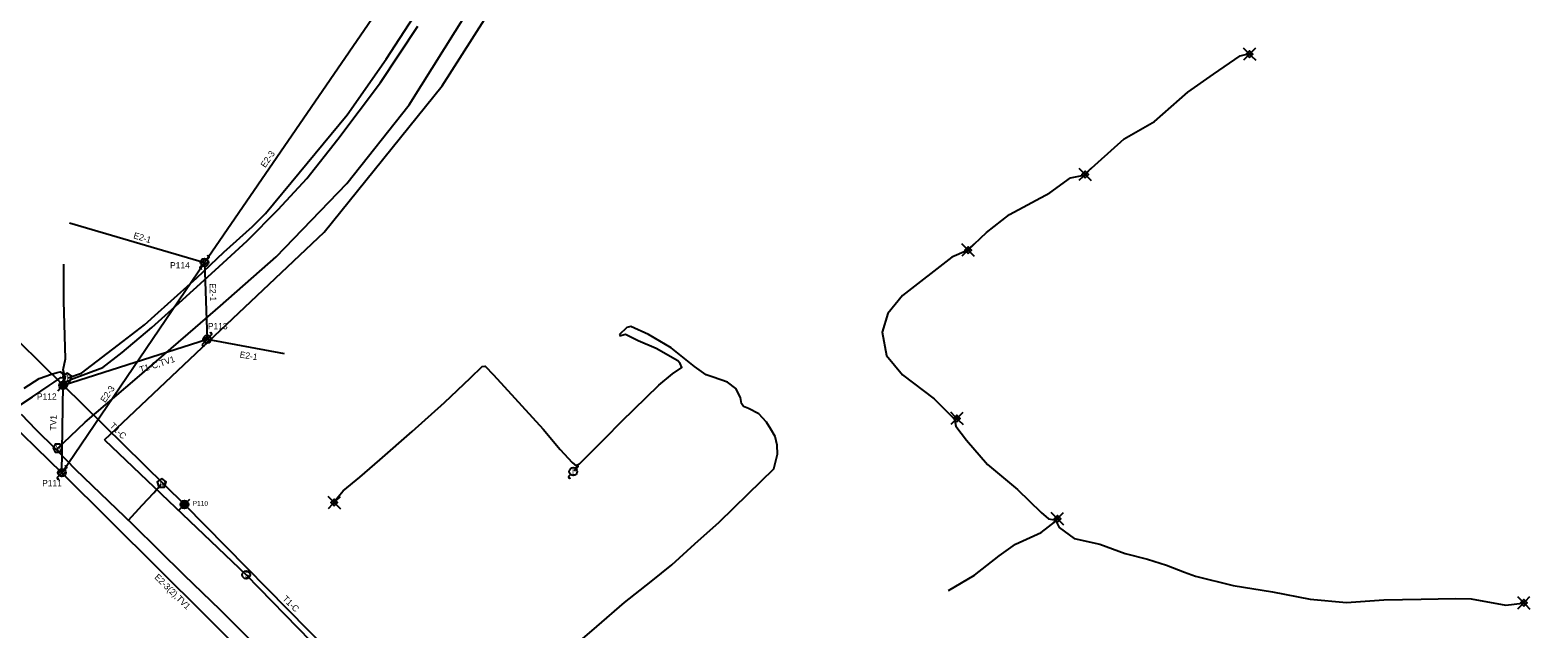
# Model space of a CAD drawing. Extents: x 1741604 to 1825760, y 1164229 to 1194908.
# Drawn here: x 1755425 to 1756379, y 1170189 to 1170568 of the extents above; entities that cross this region are included whole.
import ezdxf

# ---------------------------------------------------------------- set-up
doc = ezdxf.new("R2010")
doc.units = 0
for name, color, linetype in [('RD_EX_SU_Elec', 7, 'Continuous'), ('RD_EX_SU_H2O', 7, 'Continuous'), ('RD_EX_SU_Ovhd', 7, 'Continuous'), ('RD_EX_SU_Pole', 7, 'Continuous'), ('RD_EX_SU_Sewer', 7, 'Continuous'), ('RD_EX_SU_Telecom', 7, 'Continuous'), ('RD_EX_SU_TX_Pole', 7, 'Continuous')]:
    doc.layers.add(name, color=color, linetype=linetype)

# ---------------------------------------------------------------- blocks, each defined once
blk = doc.blocks.new('SUE_SMH')
at = {"layer": 'RD_EX_SU_Sewer'}
blk.add_circle((0, 0), 2.5, dxfattribs=at)
blk.add_text('S', height=3.57, dxfattribs=at).set_placement((-1.1, -1.79))

msp = doc.modelspace()

# ---------------------------------------------------------------- linework, layer by layer
at = {"layer": 'RD_EX_SU_Elec'}
msp.add_line((1755769.73, 1170288.79), (1755771.94, 1170292.51), dxfattribs=at)
for points in [[(1756092.94, 1170476.8), (1756117.55, 1170499.13), (1756136.8, 1170510.03), (1756157.82, 1170528.54), (1756174.09, 1170540.03), (1756190.91, 1170551.7), (1756196.05, 1170552.79)], [(1756018.81, 1170428.87), (1756030.47, 1170439.75), (1756045.03, 1170451.25), (1756070.52, 1170464.95), (1756083.65, 1170474.3), (1756092.12, 1170476.14)], [(1756017.8, 1170428.16), (1756008.58, 1170424.13), (1755977.33, 1170399.9), (1755968.08, 1170388.43), (1755964.43, 1170376.64), (1755967.1, 1170361.97), (1755977.19, 1170349.66), (1755997.36, 1170334.46), (1756009.95, 1170321.75)], [(1755764.15, 1170173.48), (1755783.87, 1170190.32), (1755801.35, 1170205.51), (1755818.14, 1170218.73), (1755831.29, 1170229.36), (1755845.85, 1170242.71), (1755861.2, 1170256.39), (1755879.67, 1170274.4), (1755895.87, 1170290.03), (1755898.13, 1170299.43), (1755898.05, 1170305.12), (1755896.64, 1170310.54), (1755894.02, 1170315.33), (1755891.25, 1170319.72), (1755886.27, 1170324.96), (1755879.88, 1170328.25), (1755876.6, 1170329.65), (1755875.38, 1170331.44), (1755874.71, 1170335.3), (1755871.77, 1170340.94), (1755866.63, 1170344.91), (1755857.41, 1170348.16), (1755853.09, 1170349.71), (1755845.62, 1170355.02), (1755830.83, 1170366.84), (1755816.52, 1170375.19), (1755805.26, 1170380.24), (1755802.74, 1170379.53), (1755797.92, 1170375.06)], [(1755618.1, 1170269.96), (1755623.39, 1170276.22), (1755633.75, 1170284.81), (1755646.57, 1170295.84), (1755666.96, 1170313.82), (1755687.48, 1170332.23), (1755703.98, 1170347.72), (1755711.25, 1170354.85), (1755713.07, 1170355.19), (1755718.51, 1170349.68), (1755749.77, 1170315.15), (1755760.69, 1170302.36), (1755768.14, 1170294.21), (1755770.98, 1170291.84), (1755772.95, 1170293.2), (1755780.25, 1170300.69), (1755789.11, 1170309.46), (1755799.38, 1170320.09), (1755823.12, 1170343.14), (1755831.66, 1170350.19), (1755837.58, 1170354.28), (1755836.65, 1170356.73), (1755835.13, 1170358.52), (1755821.44, 1170366.22), (1755809.99, 1170371.15), (1755802.05, 1170375.1), (1755798.27, 1170374.17)], [(1756010.36, 1170320.8), (1756011.01, 1170317.24), (1756017.76, 1170308.34), (1756030.98, 1170292.91), (1756050.1, 1170277.01), (1756065.02, 1170262.49), (1756069.77, 1170258.45), (1756073.45, 1170257.78)], [(1756006.39, 1170213.05), (1756022.78, 1170222.76), (1756038.42, 1170235.07), (1756048.77, 1170242.48), (1756065.02, 1170249.8), (1756074.27, 1170257.02)], [(1756074.51, 1170256.77), (1756076.39, 1170252.9), (1756085.89, 1170246.13), (1756102.17, 1170242.39), (1756118.29, 1170236.61), (1756132.4, 1170232.92), (1756144.33, 1170229.04), (1756155.71, 1170224.63), (1756162.64, 1170222.23), (1756186.51, 1170216.21), (1756211.5, 1170212.34), (1756235.26, 1170207.54), (1756258.17, 1170205.47), (1756281.96, 1170207.21), (1756305.43, 1170207.68), (1756327.12, 1170208.01), (1756337.21, 1170207.77), (1756359.06, 1170203.86), (1756369.7, 1170205.08)]]:
    msp.add_lwpolyline(points, dxfattribs=at)
at = {"layer": 'RD_EX_SU_H2O'}
for points in [[(1755441.66, 1170302.24), (1755460.1, 1170319.63), (1755492.98, 1170347.81), (1755529.94, 1170379.56), (1755545.71, 1170393.41), (1755580.96, 1170424.36), (1755625.65, 1170470.71), (1755664.97, 1170520.56), (1755702.01, 1170579.47)], [(1755419.51, 1170324.82), (1755428.9, 1170315.01), (1755440.94, 1170302.99), (1755442.22, 1170301.65), (1755453.83, 1170289.61), (1755469.55, 1170274.72), (1755490.11, 1170254.98), (1755522.61, 1170222.9), (1755545.21, 1170201.07), (1755581.64, 1170164.83), (1755584.47, 1170162.08), (1755603.36, 1170143.23), (1755654.48, 1170091.61), (1755673.95, 1170071.98), (1755722.41, 1170022.15)], [(1755487.36, 1170257.63), (1755496.08, 1170267.09), (1755503.52, 1170274.97), (1755508.06, 1170280.36)]]:
    msp.add_lwpolyline(points, dxfattribs=at)
for points in [[(1755445.45, 1170303.25), (1755444.01, 1170305.75), (1755441.12, 1170305.75), (1755439.68, 1170303.25), (1755441.12, 1170300.75), (1755444.01, 1170300.75)], [(1755508.49, 1170284.08), (1755505.59, 1170281.98), (1755506.7, 1170278.57), (1755510.29, 1170278.57), (1755511.39, 1170281.98)]]:
    msp.add_lwpolyline(points, close=True, dxfattribs=at)
at = {"layer": 'RD_EX_SU_Ovhd'}
for p, q in [((1755450.2, 1170445.81), (1755535.55, 1170420.8)), ((1755346.94, 1170440.97), (1755446.08, 1170343.01)), ((1755445.31, 1170287.7), (1755535.55, 1170420.8)), ((1755535.55, 1170420.8), (1755537.22, 1170372.19)), ((1755341.33, 1170388.64), (1755445.31, 1170287.7)), ((1755446.08, 1170343.01), (1755537.22, 1170372.19)), ((1755537.22, 1170372.19), (1755585.97, 1170363.18)), ((1755445.31, 1170287.7), (1755446.08, 1170343.01)), ((1755446.08, 1170343.01), (1755522.86, 1170267.55)), ((1755445.31, 1170287.7), (1755579.05, 1170154.72)), ((1755522.86, 1170267.55), (1755614.2, 1170174.75))]:
    msp.add_line(p, q, dxfattribs=at)
msp.add_lwpolyline([(1755535.55, 1170420.8), (1755660.75, 1170603.52)], dxfattribs=at)
at = {"layer": 'RD_EX_SU_Pole'}
for p, q in [((1756195.84, 1170551.64), (1756193.01, 1170548.81)), ((1756195.89, 1170553.74), (1756193.07, 1170556.57)), ((1756197.98, 1170553.8), (1756200.82, 1170556.64)), ((1756198.01, 1170551.62), (1756200.84, 1170548.79)), ((1756091.76, 1170475.43), (1756088.93, 1170472.61)), ((1756091.81, 1170477.54), (1756088.98, 1170480.37)), ((1756093.89, 1170477.6), (1756096.73, 1170480.44)), ((1756093.93, 1170475.42), (1756096.76, 1170472.59)), ((1756017.64, 1170427.59), (1756014.81, 1170424.77)), ((1756017.69, 1170429.7), (1756014.86, 1170432.53)), ((1756019.77, 1170429.75), (1756022.61, 1170432.59)), ((1756019.81, 1170427.58), (1756022.64, 1170424.75)), ((1755532.72, 1170417.97), (1755533.78, 1170419.03)), ((1755533.13, 1170420.15), (1755536.19, 1170423.21)), ((1755533.78, 1170419.03), (1755537.31, 1170422.57)), ((1755534.9, 1170418.38), (1755537.96, 1170421.45)), ((1755537.31, 1170422.57), (1755538.37, 1170423.63)), ((1755534.39, 1170369.36), (1755535.45, 1170370.42)), ((1755534.81, 1170371.54), (1755537.87, 1170374.6)), ((1755535.45, 1170370.42), (1755538.99, 1170373.95)), ((1755536.57, 1170369.77), (1755539.64, 1170372.83)), ((1755538.99, 1170373.95), (1755540.05, 1170375.01)), ((1756010.61, 1170321), (1756007.78, 1170318.17)), ((1756010.66, 1170323.11), (1756007.83, 1170325.93)), ((1756012.75, 1170323.16), (1756015.59, 1170326)), ((1756012.78, 1170320.98), (1756015.61, 1170318.16)), ((1755442.48, 1170284.87), (1755443.54, 1170285.93)), ((1755442.89, 1170287.05), (1755445.96, 1170290.12)), ((1755443.54, 1170285.93), (1755447.08, 1170289.47)), ((1755444.66, 1170285.29), (1755447.72, 1170288.35)), ((1755447.08, 1170289.47), (1755448.14, 1170290.53)), ((1755766.08, 1170285.56), (1755767.14, 1170286.62)), ((1755770.68, 1170290.16), (1755771.74, 1170291.22)), ((1755616.64, 1170269.8), (1755613.81, 1170272.63)), ((1755618.72, 1170269.86), (1755621.56, 1170272.7)), ((1755519.44, 1170264.12), (1755521.1, 1170265.78)), ((1755520.38, 1170267.22), (1755523.2, 1170270.03)), ((1755520.77, 1170266.18), (1755524.23, 1170269.64)), ((1755521.47, 1170265.47), (1755524.94, 1170268.94)), ((1755522.49, 1170265.07), (1755525.34, 1170267.93)), ((1755524.39, 1170265.56), (1755524.85, 1170266.02)), ((1755524.63, 1170269.32), (1755526.29, 1170270.97)), ((1755616.59, 1170267.69), (1755613.76, 1170264.87)), ((1755618.76, 1170267.68), (1755621.59, 1170264.85)), ((1756074.19, 1170257.51), (1756071.37, 1170254.68)), ((1756074.24, 1170259.61), (1756071.42, 1170262.44)), ((1756076.33, 1170259.67), (1756079.17, 1170262.51)), ((1756076.37, 1170257.49), (1756079.19, 1170254.66)), ((1756369.43, 1170206.3), (1756366.6, 1170209.13)), ((1756371.51, 1170206.36), (1756374.35, 1170209.2)), ((1756369.37, 1170204.19), (1756366.55, 1170201.37)), ((1756371.55, 1170204.18), (1756374.37, 1170201.35))]:
    msp.add_line(p, q, dxfattribs=at)
for points in [[(1756196.95, 1170550.56), (1756199.08, 1170552.68), (1756196.95, 1170554.8), (1756194.83, 1170552.68)], [(1756196.95, 1170551.98), (1756197.66, 1170552.68), (1756196.95, 1170553.39), (1756196.25, 1170552.68)], [(1756092.87, 1170474.36), (1756094.99, 1170476.48), (1756092.87, 1170478.6), (1756090.75, 1170476.48)], [(1756092.87, 1170475.77), (1756093.58, 1170476.48), (1756092.87, 1170477.19), (1756092.16, 1170476.48)], [(1756018.75, 1170426.52), (1756020.87, 1170428.64), (1756018.75, 1170430.76), (1756016.63, 1170428.64)], [(1756018.75, 1170427.93), (1756019.45, 1170428.64), (1756018.75, 1170429.35), (1756018.04, 1170428.64)], [(1756011.72, 1170319.92), (1756013.84, 1170322.04), (1756011.72, 1170324.17), (1756009.6, 1170322.04)], [(1756011.72, 1170321.34), (1756012.43, 1170322.04), (1756011.72, 1170322.75), (1756011.02, 1170322.04)], [(1755617.7, 1170266.62), (1755619.82, 1170268.74), (1755617.7, 1170270.86), (1755615.58, 1170268.74)], [(1755617.7, 1170268.03), (1755618.41, 1170268.74), (1755617.7, 1170269.45), (1755616.99, 1170268.74)], [(1756075.31, 1170256.43), (1756077.43, 1170258.55), (1756075.31, 1170260.67), (1756073.18, 1170258.55)], [(1756075.31, 1170257.85), (1756076.01, 1170258.55), (1756075.31, 1170259.26), (1756074.6, 1170258.55)], [(1756370.49, 1170203.12), (1756372.61, 1170205.24), (1756370.49, 1170207.36), (1756368.36, 1170205.24)], [(1756370.49, 1170204.53), (1756371.19, 1170205.24), (1756370.49, 1170205.95), (1756369.78, 1170205.24)]]:
    msp.add_lwpolyline(points, close=True, dxfattribs=at)
for centre in [(1755535.55, 1170420.8), (1755537.22, 1170372.19), (1755445.31, 1170287.7), (1755768.91, 1170288.39), (1755522.86, 1170267.55)]:
    msp.add_circle(centre, 2.5, dxfattribs=at)
for centre, start, end in [((1755533.25, 1170417.44), 135, 315), ((1755537.84, 1170424.16), 315, 135), ((1755534.92, 1170368.83), 135, 315), ((1755539.52, 1170375.54), 315, 135), ((1755447.61, 1170291.06), 315, 135), ((1755771.21, 1170291.75), 315, 135), ((1755443.01, 1170284.34), 135, 315), ((1755766.61, 1170285.03), 135, 315)]:
    msp.add_arc(centre, 0.75, start, end, dxfattribs=at)
at = {"layer": 'RD_EX_SU_Sewer'}
for points in [[(1755472.28, 1170308.43), (1755611.28, 1170440.07), (1755685.92, 1170532.6), (1755771.11, 1170666.36), (1755900.75, 1170895.13), (1755970.93, 1170995.72), (1756034.36, 1171088.88), (1756090.2, 1171167.02), (1756147.55, 1171225.76), (1756231.9, 1171306.77), (1756311.52, 1171366.34), (1756443.61, 1171443.81), (1756596.95, 1171527.35), (1756716.89, 1171571.4), (1756861.63, 1171600.26), (1756930.46, 1171628.36), (1757060.01, 1171710.39), (1757108.59, 1171767.1), (1757159.2, 1171859.25), (1757206.77, 1171953.42), (1757250.3, 1172017.89), (1757282.69, 1172067.18)], [(1755472.28, 1170308.43), (1755562.01, 1170223), (1755684.15, 1170097.75), (1755848.2, 1169927.49), (1755891.42, 1169870.58), (1755920.4, 1169827.47), (1756045.49, 1169608.65)]]:
    msp.add_lwpolyline(points, dxfattribs=at)
at = {"layer": 'RD_EX_SU_Telecom'}
for p, q in [((1755442.66, 1170339.59), (1755444.31, 1170341.24)), ((1755443.6, 1170342.68), (1755446.41, 1170345.49)), ((1755443.99, 1170341.65), (1755447.45, 1170345.11)), ((1755444.69, 1170340.93), (1755448.16, 1170344.41)), ((1755445.7, 1170340.54), (1755448.56, 1170343.39)), ((1755447.61, 1170341.02), (1755448.07, 1170341.49)), ((1755447.85, 1170344.78), (1755449.51, 1170346.43))]:
    msp.add_line(p, q, dxfattribs=at)
for points in [[(1755449.11, 1170347.65), (1755457.73, 1170350.8), (1755483.9, 1170370.75), (1755497.68, 1170381.21), (1755506.16, 1170389.1), (1755530.61, 1170411.02), (1755547.76, 1170427.26), (1755566.03, 1170443.65), (1755574.14, 1170451.88), (1755595.4, 1170477.57), (1755625.82, 1170514.33), (1755650.49, 1170549.56), (1755673.65, 1170585.08)], [(1755446.79, 1170344.44), (1755451.4, 1170346.81), (1755460.49, 1170350.22), (1755471.27, 1170354.25), (1755483.52, 1170363.87), (1755502.25, 1170379.57), (1755514.96, 1170391), (1755542.24, 1170415.97), (1755562.47, 1170434.47), (1755582.15, 1170454.24), (1755600.22, 1170474.01), (1755619.93, 1170498.75), (1755647, 1170534.73), (1755670.61, 1170570.42)], [(1755445.25, 1170344.06), (1755446.67, 1170346.87), (1755446.7, 1170350.47), (1755446.14, 1170352.74), (1755447.49, 1170359.74), (1755446.59, 1170396.26), (1755446.48, 1170419.76)], [(1755421.33, 1170341.29), (1755431, 1170347.4), (1755438.64, 1170350.17), (1755442.41, 1170351.15), (1755444.23, 1170351.54), (1755445.28, 1170351), (1755446.51, 1170349.43), (1755447.78, 1170348.08)], [(1755416.15, 1170328.72), (1755426.62, 1170335.77), (1755437.27, 1170342.91), (1755440.35, 1170345.05), (1755442.42, 1170346.51), (1755444.68, 1170348.06), (1755447.73, 1170347.81)], [(1755447.47, 1170347.06), (1755446.12, 1170345.44), (1755445.81, 1170344.48)]]:
    msp.add_lwpolyline(points, dxfattribs=at)
msp.add_lwpolyline([(1755448.64, 1170350.83), (1755445.79, 1170348.76), (1755446.88, 1170345.41), (1755450.41, 1170345.41), (1755451.49, 1170348.76)], close=True, dxfattribs=at)
msp.add_circle((1755446.08, 1170343.01), 2.5, dxfattribs=at)

# ---------------------------------------------------------------- block references
at = {"layer": 'RD_EX_SU_Sewer'}
msp.add_blockref('SUE_SMH', (1755561.91, 1170223), dxfattribs=at)

# ---------------------------------------------------------------- texts
at = {"layer": 'RD_EX_SU_H2O'}
for s, p in [('V', (1755441.36, 1170301.37)), ('M', (1755507.12, 1170279.04))]:
    msp.add_text(s, height=3.75, dxfattribs=at).set_placement(p)
at = {"layer": 'RD_EX_SU_Ovhd'}
for s, rotation, p in [('E2-3', 55.57905, (1755574, 1170480.45)), ('E2-1', 343.66893, (1755490.25, 1170436.16)), ('E2-1', 271.97317, (1755538.69, 1170407.53)), ('T1-C,TV1', 17.75179, (1755495.15, 1170350.89)), ('E2-1', 351.26625, (1755557.63, 1170360.6)), ('E2-3', 55.86348, (1755472.66, 1170331.68)), ('TV1', 89.19759, (1755441.79, 1170314.38)), ('T1-C', 315.60508, (1755475.26, 1170316.95)), ('E2-3(2),TV1', 315.55161, (1755503.53, 1170221.12)), ('T1-C', 315.60508, (1755584.55, 1170207.46))]:
    msp.add_text(s, height=4, rotation=rotation, dxfattribs=at).set_placement(p)
at = {"layer": 'RD_EX_SU_Pole'}
msp.add_text('L', height=4, dxfattribs=at).set_placement((1755768.05, 1170286.39))
at = {"layer": 'RD_EX_SU_Telecom'}
msp.add_text('T', height=3.75, dxfattribs=at).set_placement((1755447.39, 1170345.96))
at = {"layer": 'RD_EX_SU_TX_Pole'}
for s, height, p in [('P114', 4, (1755513.74, 1170416.99)), ('P113', 4, (1755537.68, 1170378.47)), ('P112', 4, (1755429.51, 1170333.94)), ('P111', 4, (1755432.81, 1170279.1)), ('P110', 3, (1755528.09, 1170266.81))]:
    msp.add_text(s, height=height, dxfattribs=at).set_placement(p)

doc.saveas('drawing.dxf')
